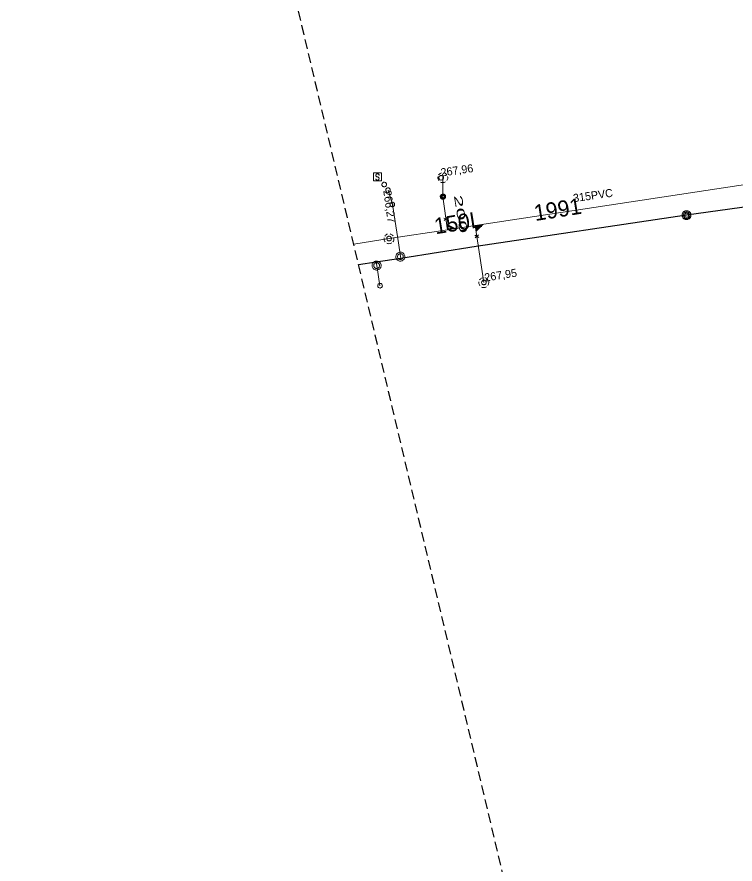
# Model space of a CAD drawing. Extents: x -732096 to -731933, y -1048703 to -1047964.
# Drawn here: x -732095.3 to -732023.8, y -1048617 to -1048532.6 of the extents above; entities that cross this region are included whole.
import ezdxf

# ---------------------------------------------------------------- set-up
doc = ezdxf.new("R2010")
doc.units = 0
doc.header["$LTSCALE"] = 0.32
doc.linetypes.add('MEDIUM_DASHED', pattern=[4.5, 3, -1.5])
doc.layers.add('1', color=7, linetype='Continuous')
for name, color, linetype, lineweight in [('18', 7, 'Continuous', 13), ('20', 7, 'Continuous', 13), ('49', 7, 'Continuous', 13), ('63', 7, 'MEDIUM_DASHED', 25), ('8', 7, 'Continuous', 13)]:
    doc.layers.add(name, color=color, linetype=linetype, lineweight=lineweight)

msp = doc.modelspace()

# ---------------------------------------------------------------- linework, layer by layer
at = {"layer": '18'}
for p, q in [((-732052.797, -1048552.654), (-732052.393, -1048552.84)), ((-732052.463, -1048552.591), (-732052.754, -1048552.907)), ((-732049.328, -1048554.595), (-732049.7, -1048554.379)), ((-732049.664, -1048554.633), (-732049.334, -1048554.336))]:
    msp.add_line(p, q, dxfattribs=at)
for points in [[(-732053.043, -1048548.167), (-732053.114, -1048548.195), (-732053.181, -1048548.234), (-732053.241, -1048548.282), (-732053.292, -1048548.339), (-732053.316, -1048548.373)], [(-732052.502, -1048548.35), (-732052.552, -1048548.292), (-732052.61, -1048548.242), (-732052.675, -1048548.201), (-732052.746, -1048548.172), (-732052.795, -1048548.158)], [(-732053.388, -1048548.559), (-732053.394, -1048548.636), (-732053.389, -1048548.713), (-732053.372, -1048548.788), (-732053.343, -1048548.859), (-732053.303, -1048548.925), (-732053.287, -1048548.947)], [(-732053.13, -1048549.076), (-732053.06, -1048549.107), (-732052.985, -1048549.126), (-732052.909, -1048549.133), (-732052.832, -1048549.128), (-732052.757, -1048549.111), (-732052.685, -1048549.083), (-732052.625, -1048549.048)], [(-732052.507, -1048548.936), (-732052.466, -1048548.871), (-732052.435, -1048548.801), (-732052.416, -1048548.726), (-732052.408, -1048548.65), (-732052.413, -1048548.573), (-732052.419, -1048548.538)], [(-732052.603, -1048552.743), (-732052.439, -1048553.826), (-732051.677, -1048553.711), (-732052.526, -1048553.255)], [(-732052.457, -1048553.364), (-732052.395, -1048553.775), (-732051.836, -1048553.69), (-732052.458, -1048553.363)], [(-732052.398, -1048553.44), (-732052.355, -1048553.727), (-732051.988, -1048553.672), (-732052.4, -1048553.44)], [(-732049.506, -1048554.491), (-732049.67, -1048553.408), (-732048.908, -1048553.293), (-732049.583, -1048553.98)], [(-732049.552, -1048553.855), (-732049.614, -1048553.444), (-732049.054, -1048553.36), (-732049.551, -1048553.857)], [(-732049.518, -1048553.766), (-732049.561, -1048553.477), (-732049.193, -1048553.421), (-732049.519, -1048553.766)], [(-732058.748, -1048554.639), (-732058.754, -1048554.716), (-732058.749, -1048554.793), (-732058.732, -1048554.868), (-732058.703, -1048554.939), (-732058.663, -1048555.005), (-732058.647, -1048555.027)], [(-732058.403, -1048554.247), (-732058.474, -1048554.275), (-732058.541, -1048554.314), (-732058.601, -1048554.362), (-732058.652, -1048554.419), (-732058.676, -1048554.453)], [(-732057.862, -1048554.43), (-732057.912, -1048554.372), (-732057.97, -1048554.322), (-732058.035, -1048554.281), (-732058.106, -1048554.252), (-732058.155, -1048554.238)], [(-732057.867, -1048555.016), (-732057.826, -1048554.951), (-732057.795, -1048554.881), (-732057.776, -1048554.806), (-732057.768, -1048554.73), (-732057.773, -1048554.653), (-732057.779, -1048554.618)], [(-732058.49, -1048555.156), (-732058.42, -1048555.187), (-732058.345, -1048555.206), (-732058.269, -1048555.213), (-732058.192, -1048555.208), (-732058.117, -1048555.191), (-732058.045, -1048555.163), (-732057.985, -1048555.128)], [(-732049.307, -1048559.009), (-732049.313, -1048559.086), (-732049.308, -1048559.163), (-732049.291, -1048559.238), (-732049.262, -1048559.309), (-732049.222, -1048559.375), (-732049.206, -1048559.397)], [(-732048.962, -1048558.617), (-732049.033, -1048558.645), (-732049.1, -1048558.684), (-732049.16, -1048558.732), (-732049.211, -1048558.789), (-732049.235, -1048558.823)], [(-732048.421, -1048558.8), (-732048.471, -1048558.742), (-732048.529, -1048558.692), (-732048.594, -1048558.651), (-732048.665, -1048558.622), (-732048.714, -1048558.608)], [(-732048.426, -1048559.386), (-732048.385, -1048559.321), (-732048.354, -1048559.251), (-732048.335, -1048559.176), (-732048.327, -1048559.1), (-732048.332, -1048559.023), (-732048.338, -1048558.988)], [(-732049.049, -1048559.526), (-732048.979, -1048559.557), (-732048.904, -1048559.576), (-732048.828, -1048559.583), (-732048.751, -1048559.578), (-732048.676, -1048559.561), (-732048.604, -1048559.533), (-732048.544, -1048559.498)]]:
    msp.add_lwpolyline(points, dxfattribs=at)
for points in [[(-732052.838, -1048548.649), (-732052.845, -1048548.597), (-732052.862, -1048548.547), (-732052.891, -1048548.503), (-732052.929, -1048548.466), (-732052.973, -1048548.439), (-732053.024, -1048548.423), (-732053.076, -1048548.418), (-732053.127, -1048548.425), (-732053.176, -1048548.444), (-732053.22, -1048548.474), (-732053.255, -1048548.513), (-732053.282, -1048548.558), (-732053.296, -1048548.609), (-732053.299, -1048548.661), (-732053.291, -1048548.713), (-732053.271, -1048548.761), (-732053.24, -1048548.804), (-732053.201, -1048548.839), (-732053.154, -1048548.863), (-732053.103, -1048548.877), (-732053.051, -1048548.879), (-732053, -1048548.869), (-732052.951, -1048548.847), (-732052.909, -1048548.815), (-732052.877, -1048548.775), (-732052.853, -1048548.728), (-732052.84, -1048548.677)], [(-732052.625, -1048550.527), (-732052.63, -1048550.471), (-732052.647, -1048550.418), (-732052.676, -1048550.369), (-732052.715, -1048550.328), (-732052.761, -1048550.296), (-732052.813, -1048550.274), (-732052.868, -1048550.263), (-732052.924, -1048550.265), (-732052.978, -1048550.278), (-732053.029, -1048550.303), (-732053.074, -1048550.338), (-732053.11, -1048550.381), (-732053.135, -1048550.431), (-732053.15, -1048550.486), (-732053.152, -1048550.542), (-732053.144, -1048550.597), (-732053.123, -1048550.65), (-732053.092, -1048550.696), (-732053.051, -1048550.735), (-732053.004, -1048550.765), (-732052.951, -1048550.784), (-732052.895, -1048550.791), (-732052.838, -1048550.787), (-732052.784, -1048550.77), (-732052.735, -1048550.743), (-732052.694, -1048550.705), (-732052.661, -1048550.66), (-732052.637, -1048550.609), (-732052.625, -1048550.554)], [(-732052.684, -1048550.53), (-732052.69, -1048550.481), (-732052.708, -1048550.435), (-732052.735, -1048550.394), (-732052.772, -1048550.361), (-732052.816, -1048550.339), (-732052.865, -1048550.327), (-732052.914, -1048550.327), (-732052.962, -1048550.339), (-732053.005, -1048550.362), (-732053.043, -1048550.395), (-732053.071, -1048550.436), (-732053.088, -1048550.483), (-732053.093, -1048550.532), (-732053.087, -1048550.581), (-732053.069, -1048550.627), (-732053.041, -1048550.667), (-732053.004, -1048550.7), (-732052.96, -1048550.722), (-732052.911, -1048550.734), (-732052.862, -1048550.733), (-732052.814, -1048550.721), (-732052.771, -1048550.697), (-732052.733, -1048550.664), (-732052.706, -1048550.623), (-732052.69, -1048550.576)], [(-732052.743, -1048550.534), (-732052.749, -1048550.492), (-732052.766, -1048550.454), (-732052.794, -1048550.423), (-732052.828, -1048550.4), (-732052.869, -1048550.389), (-732052.911, -1048550.389), (-732052.951, -1048550.401), (-732052.985, -1048550.424), (-732053.012, -1048550.456), (-732053.029, -1048550.494), (-732053.034, -1048550.535), (-732053.029, -1048550.577), (-732053.011, -1048550.614), (-732052.983, -1048550.646), (-732052.946, -1048550.668), (-732052.907, -1048550.679), (-732052.865, -1048550.678), (-732052.825, -1048550.665), (-732052.791, -1048550.642), (-732052.764, -1048550.609), (-732052.748, -1048550.571)], [(-732058.019, -1048554.699), (-732058.025, -1048554.647), (-732058.043, -1048554.597), (-732058.071, -1048554.553), (-732058.109, -1048554.516), (-732058.154, -1048554.489), (-732058.204, -1048554.473), (-732058.256, -1048554.468), (-732058.308, -1048554.475), (-732058.357, -1048554.494), (-732058.401, -1048554.524), (-732058.436, -1048554.563), (-732058.462, -1048554.608), (-732058.477, -1048554.659), (-732058.48, -1048554.711), (-732058.472, -1048554.763), (-732058.451, -1048554.811), (-732058.421, -1048554.854), (-732058.381, -1048554.889), (-732058.335, -1048554.913), (-732058.284, -1048554.927), (-732058.232, -1048554.929), (-732058.18, -1048554.919), (-732058.132, -1048554.897), (-732058.09, -1048554.865), (-732058.057, -1048554.825), (-732058.033, -1048554.778), (-732058.021, -1048554.727)], [(-732048.578, -1048559.069), (-732048.584, -1048559.017), (-732048.602, -1048558.967), (-732048.63, -1048558.923), (-732048.668, -1048558.886), (-732048.713, -1048558.859), (-732048.763, -1048558.843), (-732048.815, -1048558.838), (-732048.867, -1048558.845), (-732048.916, -1048558.864), (-732048.96, -1048558.894), (-732048.995, -1048558.933), (-732049.021, -1048558.978), (-732049.036, -1048559.029), (-732049.039, -1048559.081), (-732049.031, -1048559.133), (-732049.01, -1048559.181), (-732048.98, -1048559.224), (-732048.94, -1048559.259), (-732048.894, -1048559.283), (-732048.843, -1048559.297), (-732048.791, -1048559.299), (-732048.739, -1048559.289), (-732048.691, -1048559.267), (-732048.649, -1048559.235), (-732048.616, -1048559.195), (-732048.592, -1048559.148), (-732048.58, -1048559.097)]]:
    msp.add_lwpolyline(points, close=True, dxfattribs=at)
at = {"layer": '20'}
msp.add_line((-732061.776, -1048555.26), (-732058.25, -1048554.71), dxfattribs=at)
msp.add_line((-732061.776, -1048555.26), (-732058.25, -1048554.71), dxfattribs=at)
msp.add_lwpolyline([(-732058.25, -1048554.71), (-732052.436, -1048553.829), (-732049.668, -1048553.41), (-732019.71, -1048548.87)], dxfattribs=at)
msp.add_lwpolyline([(-732058.25, -1048554.71), (-732052.436, -1048553.829), (-732049.668, -1048553.41), (-732019.71, -1048548.87)], dxfattribs=at)
at = {"layer": '49'}
msp.add_line((-732048.809, -1048559.08), (-732049.668, -1048553.41), dxfattribs=at)
msp.add_line((-732048.809, -1048559.08), (-732049.668, -1048553.41), dxfattribs=at)
msp.add_lwpolyline([(-732052.89, -1048548.63), (-732052.889, -1048550.54), (-732052.436, -1048553.829)], dxfattribs=at)
msp.add_lwpolyline([(-732052.89, -1048548.63), (-732052.889, -1048550.54), (-732052.436, -1048553.829)], dxfattribs=at)
at = {"layer": '63'}
msp.add_lwpolyline([(-732027.835, -1048396.578), (-731958.19, -1048580.745), (-731958.189, -1048580.746), (-731932.909, -1048703.246), (-731932.908, -1048703.248), (-731932.909, -1048703.25), (-731932.909, -1048703.251), (-731932.91, -1048703.253), (-731932.911, -1048703.255), (-731932.913, -1048703.256), (-731932.914, -1048703.257), (-731932.916, -1048703.257), (-731932.918, -1048703.258), (-731932.92, -1048703.258), (-732030.18, -1048688.546), (-732030.182, -1048688.545), (-732030.184, -1048688.545), (-732030.185, -1048688.543), (-732030.186, -1048688.542), (-732030.187, -1048688.54), (-732030.188, -1048688.538), (-732095.318, -1048413.733)], dxfattribs=at)
at = {"layer": '8'}
for p, q in [((-732057.92, -1048551.31), (-732058.35, -1048549.87)), ((-732057.09, -1048556.69), (-732057.12, -1048556.5)), ((-732059.533, -1048557.048), (-732059.48, -1048557.39)), ((-732059.48, -1048557.39), (-732059.164, -1048559.394))]:
    msp.add_line(p, q, dxfattribs=at)
for points in [[(-732059.801, -1048548.162), (-732059.011, -1048548.162), (-732059.011, -1048548.962), (-732059.801, -1048548.962)], [(-732058.507, -1048549.319), (-732058.514, -1048549.267), (-732058.531, -1048549.217), (-732058.559, -1048549.173), (-732058.598, -1048549.136), (-732058.642, -1048549.109), (-732058.693, -1048549.093), (-732058.745, -1048549.088), (-732058.796, -1048549.095), (-732058.845, -1048549.114), (-732058.889, -1048549.144), (-732058.924, -1048549.183), (-732058.951, -1048549.228), (-732058.965, -1048549.279), (-732058.968, -1048549.331), (-732058.96, -1048549.383), (-732058.94, -1048549.431), (-732058.909, -1048549.474), (-732058.87, -1048549.509), (-732058.823, -1048549.533), (-732058.772, -1048549.547), (-732058.72, -1048549.549), (-732058.669, -1048549.539), (-732058.62, -1048549.517), (-732058.578, -1048549.485), (-732058.546, -1048549.445), (-732058.522, -1048549.398), (-732058.509, -1048549.347)], [(-732058.426, -1048549.651), (-732058.474, -1048549.672), (-732058.517, -1048549.703), (-732058.551, -1048549.743), (-732058.575, -1048549.79), (-732058.588, -1048549.841), (-732058.589, -1048549.893), (-732058.579, -1048549.944), (-732058.558, -1048549.992), (-732058.525, -1048550.034), (-732058.484, -1048550.067), (-732058.437, -1048550.09), (-732058.386, -1048550.102), (-732058.333, -1048550.101), (-732058.282, -1048550.089), (-732058.235, -1048550.067), (-732058.195, -1048550.033), (-732058.162, -1048549.992), (-732058.14, -1048549.944), (-732058.13, -1048549.893), (-732058.131, -1048549.84), (-732058.144, -1048549.789), (-732058.169, -1048549.742), (-732058.204, -1048549.703), (-732058.246, -1048549.672), (-732058.294, -1048549.652), (-732058.346, -1048549.642), (-732058.398, -1048549.645)], [(-732057.965, -1048551.083), (-732058.016, -1048551.097), (-732058.062, -1048551.122), (-732058.101, -1048551.156), (-732058.132, -1048551.2), (-732058.152, -1048551.248), (-732058.16, -1048551.3), (-732058.157, -1048551.352), (-732058.142, -1048551.403), (-732058.116, -1048551.448), (-732058.08, -1048551.487), (-732058.036, -1048551.516), (-732057.988, -1048551.534), (-732057.935, -1048551.542), (-732057.883, -1048551.537), (-732057.833, -1048551.521), (-732057.789, -1048551.493), (-732057.751, -1048551.457), (-732057.722, -1048551.412), (-732057.705, -1048551.363), (-732057.699, -1048551.31), (-732057.705, -1048551.258), (-732057.723, -1048551.208), (-732057.752, -1048551.164), (-732057.79, -1048551.128), (-732057.835, -1048551.101), (-732057.885, -1048551.085), (-732057.937, -1048551.081)], [(-732028.303, -1048552.377), (-732028.309, -1048552.316), (-732028.327, -1048552.256), (-732028.356, -1048552.201), (-732028.395, -1048552.153), (-732028.442, -1048552.113), (-732028.496, -1048552.083), (-732028.555, -1048552.063), (-732028.617, -1048552.056), (-732028.679, -1048552.06), (-732028.739, -1048552.076), (-732028.794, -1048552.104), (-732028.844, -1048552.141), (-732028.885, -1048552.188), (-732028.917, -1048552.241), (-732028.937, -1048552.3), (-732028.947, -1048552.361), (-732028.944, -1048552.423), (-732028.929, -1048552.483), (-732028.903, -1048552.54), (-732028.867, -1048552.59), (-732028.821, -1048552.633), (-732028.769, -1048552.665), (-732028.711, -1048552.688), (-732028.65, -1048552.698), (-732028.588, -1048552.697), (-732028.527, -1048552.684), (-732028.47, -1048552.659), (-732028.419, -1048552.624), (-732028.375, -1048552.58), (-732028.341, -1048552.528), (-732028.317, -1048552.471), (-732028.305, -1048552.41)], [(-732028.417, -1048552.377), (-732028.423, -1048552.328), (-732028.44, -1048552.281), (-732028.468, -1048552.24), (-732028.506, -1048552.207), (-732028.55, -1048552.183), (-732028.598, -1048552.171), (-732028.648, -1048552.17), (-732028.696, -1048552.182), (-732028.741, -1048552.204), (-732028.779, -1048552.237), (-732028.808, -1048552.277), (-732028.827, -1048552.324), (-732028.834, -1048552.373), (-732028.829, -1048552.423), (-732028.812, -1048552.47), (-732028.785, -1048552.512), (-732028.748, -1048552.546), (-732028.705, -1048552.57), (-732028.657, -1048552.584), (-732028.607, -1048552.585), (-732028.558, -1048552.575), (-732028.513, -1048552.553), (-732028.474, -1048552.521), (-732028.444, -1048552.482), (-732028.425, -1048552.436), (-732028.417, -1048552.386)], [(-732057.2, -1048556.06), (-732057.271, -1048556.077), (-732057.338, -1048556.106), (-732057.4, -1048556.145), (-732057.454, -1048556.194), (-732057.5, -1048556.251), (-732057.536, -1048556.314), (-732057.561, -1048556.383), (-732057.575, -1048556.455), (-732057.576, -1048556.528), (-732057.566, -1048556.601), (-732057.543, -1048556.671), (-732057.51, -1048556.736), (-732057.467, -1048556.794), (-732057.415, -1048556.846), (-732057.354, -1048556.888), (-732057.289, -1048556.919), (-732057.218, -1048556.939), (-732057.145, -1048556.948), (-732057.072, -1048556.945), (-732057.001, -1048556.929), (-732056.933, -1048556.902), (-732056.87, -1048556.865), (-732056.814, -1048556.818), (-732056.767, -1048556.762), (-732056.729, -1048556.699), (-732056.702, -1048556.631), (-732056.686, -1048556.56), (-732056.683, -1048556.486), (-732056.691, -1048556.414), (-732056.711, -1048556.343), (-732056.743, -1048556.277), (-732056.785, -1048556.217), (-732056.836, -1048556.164), (-732056.894, -1048556.121), (-732056.96, -1048556.088), (-732057.03, -1048556.065), (-732057.102, -1048556.055), (-732057.175, -1048556.057)], [(-732057.174, -1048556.219), (-732057.231, -1048556.234), (-732057.283, -1048556.26), (-732057.329, -1048556.296), (-732057.367, -1048556.341), (-732057.395, -1048556.392), (-732057.412, -1048556.448), (-732057.416, -1048556.507), (-732057.409, -1048556.566), (-732057.39, -1048556.62), (-732057.36, -1048556.671), (-732057.321, -1048556.715), (-732057.274, -1048556.749), (-732057.221, -1048556.773), (-732057.163, -1048556.786), (-732057.105, -1048556.787), (-732057.047, -1048556.776), (-732056.993, -1048556.753), (-732056.944, -1048556.72), (-732056.905, -1048556.677), (-732056.873, -1048556.628), (-732056.853, -1048556.573), (-732056.844, -1048556.515), (-732056.847, -1048556.457), (-732056.862, -1048556.4), (-732056.888, -1048556.348), (-732056.924, -1048556.302), (-732056.97, -1048556.264), (-732057.021, -1048556.237), (-732057.077, -1048556.22), (-732057.135, -1048556.216)], [(-732059.49, -1048556.942), (-732059.563, -1048556.948), (-732059.634, -1048556.966), (-732059.701, -1048556.995), (-732059.762, -1048557.035), (-732059.817, -1048557.084), (-732059.862, -1048557.141), (-732059.897, -1048557.205), (-732059.922, -1048557.274), (-732059.935, -1048557.346), (-732059.936, -1048557.42), (-732059.925, -1048557.492), (-732059.902, -1048557.562), (-732059.869, -1048557.626), (-732059.825, -1048557.685), (-732059.772, -1048557.736), (-732059.712, -1048557.777), (-732059.645, -1048557.808), (-732059.575, -1048557.828), (-732059.502, -1048557.836), (-732059.429, -1048557.833), (-732059.358, -1048557.817), (-732059.29, -1048557.79), (-732059.227, -1048557.752), (-732059.172, -1048557.704), (-732059.125, -1048557.648), (-732059.088, -1048557.585), (-732059.061, -1048557.517), (-732059.046, -1048557.445), (-732059.043, -1048557.372), (-732059.052, -1048557.299), (-732059.073, -1048557.229), (-732059.105, -1048557.163), (-732059.147, -1048557.103), (-732059.198, -1048557.051), (-732059.258, -1048557.008), (-732059.323, -1048556.975), (-732059.393, -1048556.954), (-732059.465, -1048556.944)], [(-732059.49, -1048557.103), (-732059.548, -1048557.109), (-732059.604, -1048557.127), (-732059.655, -1048557.155), (-732059.699, -1048557.194), (-732059.735, -1048557.24), (-732059.76, -1048557.293), (-732059.774, -1048557.35), (-732059.776, -1048557.409), (-732059.766, -1048557.466), (-732059.744, -1048557.521), (-732059.712, -1048557.57), (-732059.671, -1048557.611), (-732059.622, -1048557.643), (-732059.567, -1048557.665), (-732059.51, -1048557.675), (-732059.451, -1048557.674), (-732059.394, -1048557.66), (-732059.341, -1048557.635), (-732059.295, -1048557.599), (-732059.256, -1048557.555), (-732059.228, -1048557.504), (-732059.21, -1048557.448), (-732059.204, -1048557.39), (-732059.21, -1048557.332), (-732059.227, -1048557.276), (-732059.256, -1048557.225), (-732059.295, -1048557.181), (-732059.341, -1048557.146), (-732059.394, -1048557.121), (-732059.451, -1048557.107)], [(-732059.117, -1048559.62), (-732059.066, -1048559.606), (-732059.02, -1048559.58), (-732058.981, -1048559.546), (-732058.95, -1048559.502), (-732058.931, -1048559.454), (-732058.923, -1048559.402), (-732058.926, -1048559.35), (-732058.941, -1048559.299), (-732058.968, -1048559.254), (-732059.004, -1048559.215), (-732059.048, -1048559.187), (-732059.097, -1048559.168), (-732059.149, -1048559.161), (-732059.201, -1048559.167), (-732059.251, -1048559.183), (-732059.295, -1048559.211), (-732059.333, -1048559.247), (-732059.361, -1048559.292), (-732059.378, -1048559.342), (-732059.384, -1048559.394), (-732059.377, -1048559.446), (-732059.359, -1048559.496), (-732059.33, -1048559.54), (-732059.292, -1048559.576), (-732059.247, -1048559.602), (-732059.197, -1048559.619), (-732059.145, -1048559.622)]]:
    msp.add_lwpolyline(points, close=True, dxfattribs=at)
for points in [[(-732059.574, -1048548.745), (-732059.564, -1048548.788), (-732059.542, -1048548.827), (-732059.511, -1048548.858), (-732059.473, -1048548.879), (-732059.43, -1048548.89), (-732059.386, -1048548.888), (-732059.344, -1048548.875), (-732059.307, -1048548.851), (-732059.278, -1048548.818), (-732059.259, -1048548.778), (-732059.251, -1048548.735), (-732059.255, -1048548.691), (-732059.271, -1048548.65), (-732059.297, -1048548.615), (-732059.332, -1048548.588), (-732059.373, -1048548.571), (-732059.399, -1048548.566)], [(-732059.252, -1048548.408), (-732059.257, -1048548.365), (-732059.274, -1048548.324), (-732059.301, -1048548.29), (-732059.337, -1048548.264), (-732059.378, -1048548.249), (-732059.421, -1048548.246), (-732059.464, -1048548.254), (-732059.503, -1048548.274), (-732059.536, -1048548.303), (-732059.559, -1048548.341), (-732059.571, -1048548.383), (-732059.572, -1048548.426), (-732059.56, -1048548.469), (-732059.538, -1048548.506), (-732059.506, -1048548.537), (-732059.468, -1048548.557), (-732059.425, -1048548.566), (-732059.399, -1048548.566)], [(-732057.12, -1048556.5), (-732057.329, -1048555.14), (-732057.92, -1048551.31)], [(-732028.19, -1048552.369), (-732028.192, -1048552.324), (-732028.199, -1048552.279), (-732028.211, -1048552.234), (-732028.227, -1048552.192), (-732028.248, -1048552.151), (-732028.273, -1048552.112), (-732028.302, -1048552.077), (-732028.334, -1048552.044), (-732028.37, -1048552.016), (-732028.407, -1048551.991), (-732028.449, -1048551.97), (-732028.492, -1048551.953), (-732028.536, -1048551.941), (-732028.581, -1048551.934), (-732028.627, -1048551.932), (-732028.673, -1048551.934), (-732028.718, -1048551.941), (-732028.762, -1048551.953), (-732028.805, -1048551.97), (-732028.846, -1048551.991), (-732028.884, -1048552.016), (-732028.92, -1048552.044), (-732028.952, -1048552.077), (-732028.981, -1048552.112), (-732029.006, -1048552.151), (-732029.027, -1048552.192), (-732029.043, -1048552.234), (-732029.055, -1048552.279), (-732029.062, -1048552.324), (-732029.065, -1048552.37), (-732029.062, -1048552.415), (-732029.055, -1048552.46), (-732029.043, -1048552.505), (-732029.027, -1048552.547), (-732029.006, -1048552.588), (-732028.981, -1048552.627), (-732028.952, -1048552.662), (-732028.92, -1048552.695), (-732028.884, -1048552.723), (-732028.846, -1048552.748), (-732028.805, -1048552.769), (-732028.762, -1048552.786), (-732028.718, -1048552.797), (-732028.673, -1048552.805), (-732028.627, -1048552.807), (-732028.581, -1048552.805), (-732028.536, -1048552.797), (-732028.492, -1048552.786), (-732028.449, -1048552.769), (-732028.407, -1048552.748), (-732028.37, -1048552.723), (-732028.334, -1048552.695), (-732028.302, -1048552.662), (-732028.273, -1048552.627), (-732028.248, -1048552.588), (-732028.227, -1048552.547), (-732028.211, -1048552.505), (-732028.199, -1048552.46), (-732028.192, -1048552.415), (-732028.19, -1048552.37)]]:
    msp.add_lwpolyline(points, dxfattribs=at)
at = {"layer": '8', "lineweight": 25}
for points in [[(-732008.149, -1048549.18), (-732009.997, -1048549.686), (-732015.672, -1048550.592), (-732028.62, -1048552.38)], [(-732028.62, -1048552.38), (-732049.579, -1048555.48), (-732057.09, -1048556.69), (-732059.533, -1048557.048), (-732061.291, -1048557.307)]]:
    msp.add_lwpolyline(points, dxfattribs=at)

# ---------------------------------------------------------------- texts
at = {"layer": '1'}
for s, height, rotation, p in [('267,96', 0.8, 8, (-732053.063, -1048548.529)), ('266,27', 0.8, 278, (-732058.834, -1048549.944)), ('315PVC', 0.8, 8, (-732039.865, -1048551.077)), ('1991', 1.6, 9, (-732043.69, -1048552.958)), ('150L', 1.6, 9, (-732053.622, -1048554.274)), ('267,95', 0.8, 9, (-732048.698, -1048558.988))]:
    msp.add_text(s, height=height, rotation=rotation, dxfattribs=at).set_placement(p)
at = {"layer": '1', "width": 2.15}
msp.add_text('200 ', height=0.8, rotation=279, dxfattribs=at).set_placement((-732051.802, -1048550.423))

doc.saveas('drawing.dxf')
